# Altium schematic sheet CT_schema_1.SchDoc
size 445 x 258 mm
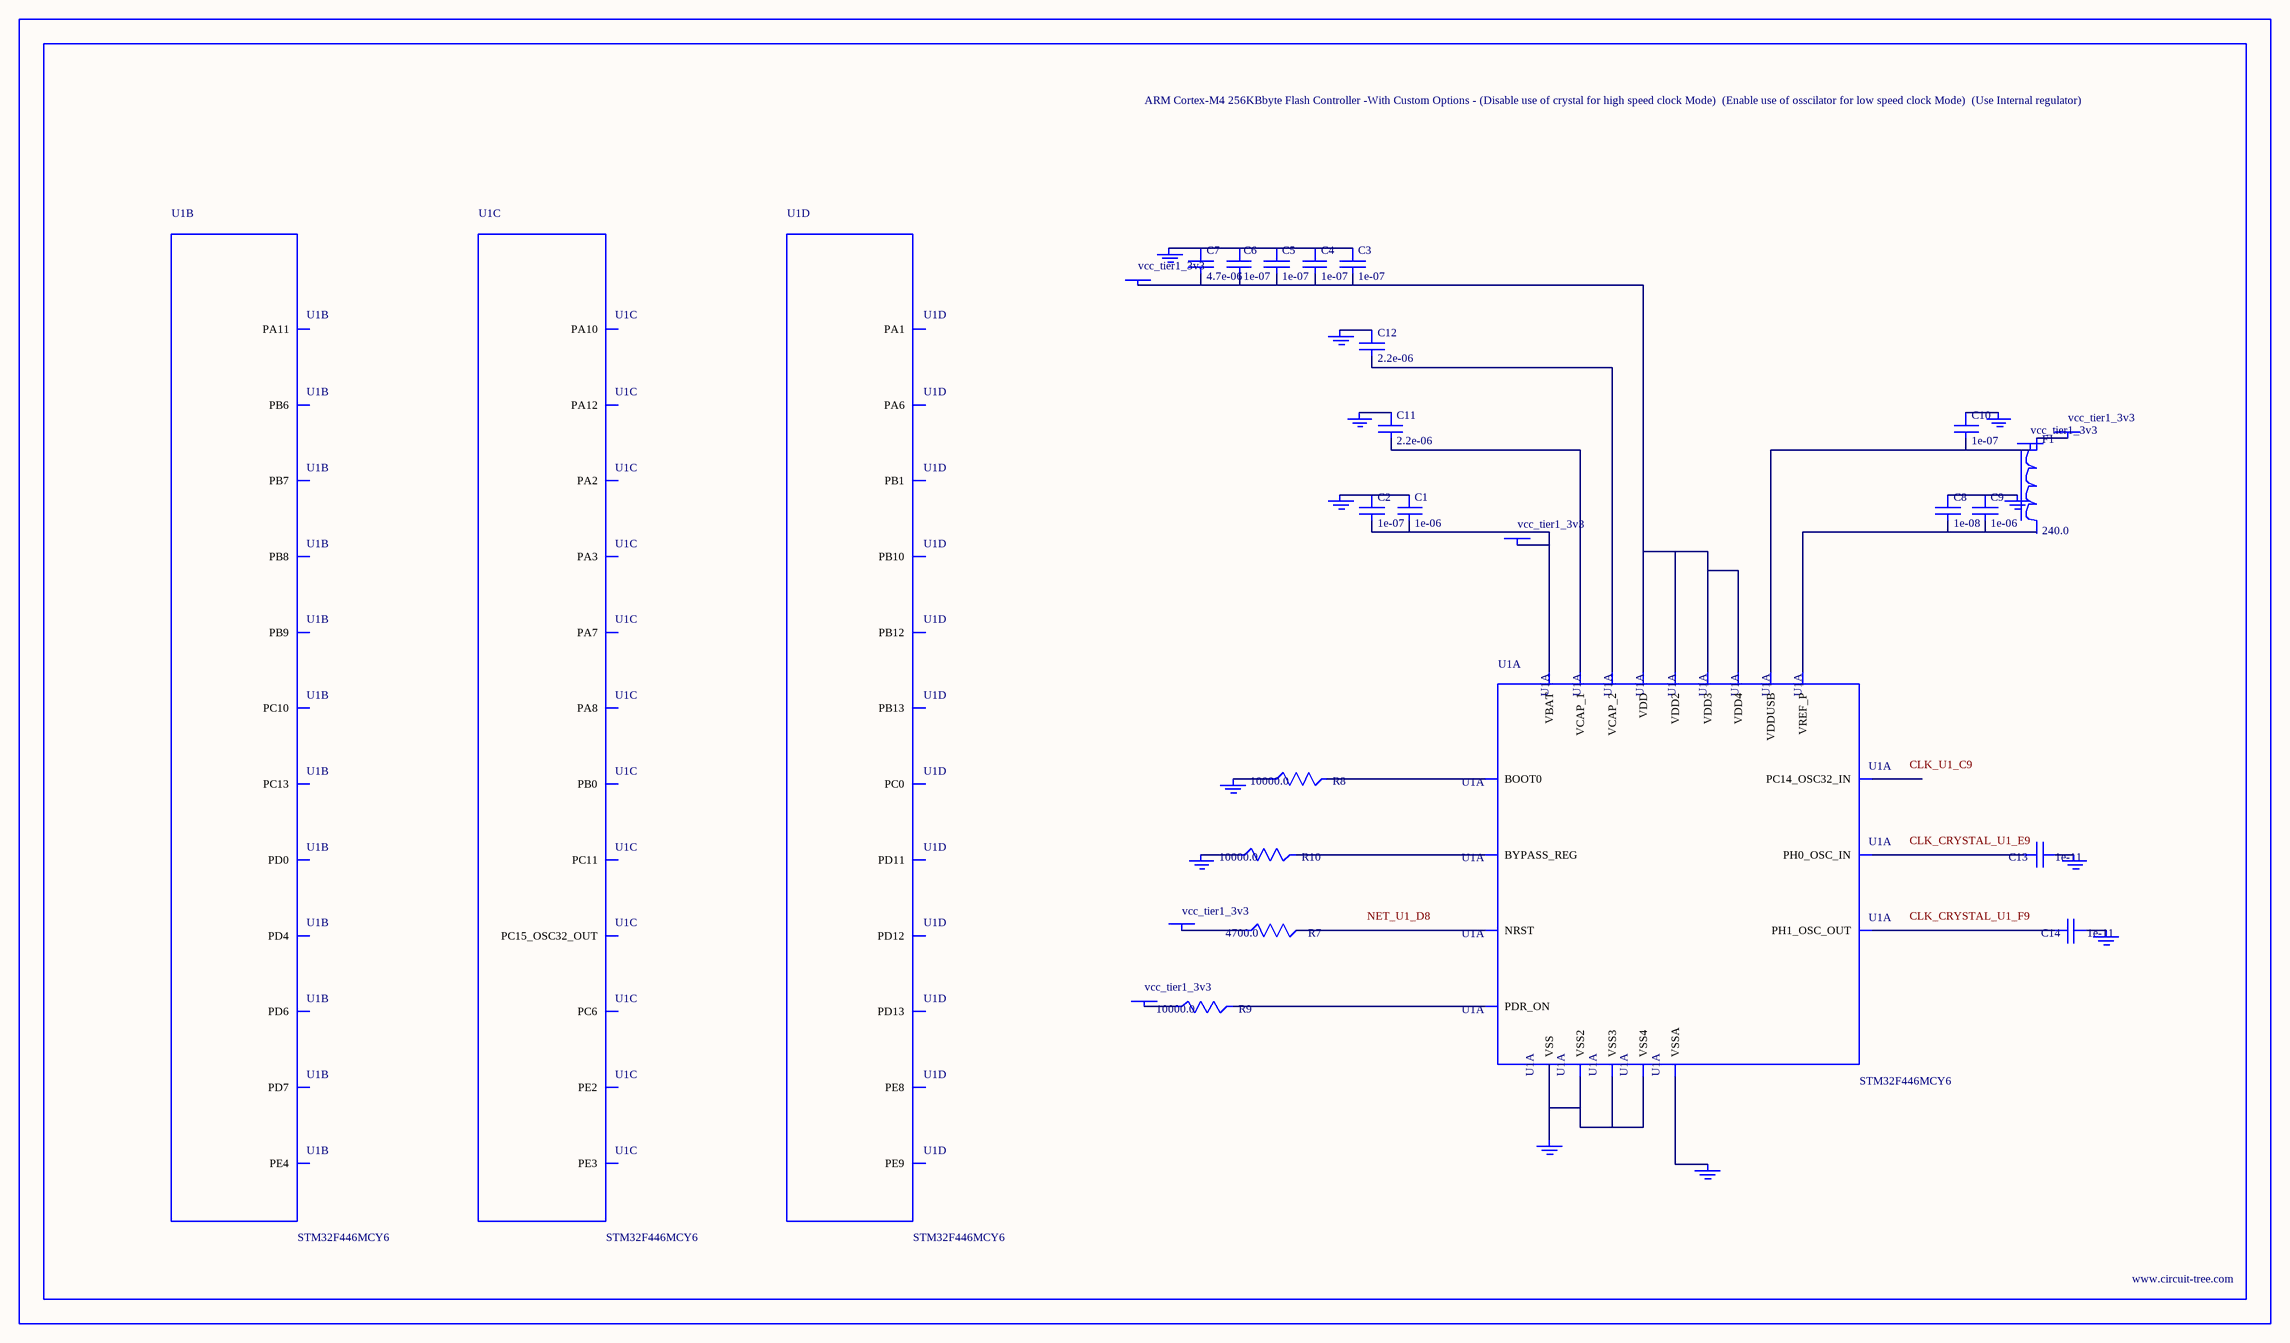
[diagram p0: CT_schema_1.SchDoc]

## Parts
BORDER0  (no value)
C1  1e-06  [C0603]
C2  1e-07  [C0603]
C3  1e-07  [C0603]
C4  1e-07  [C0603]
C5  1e-07  [C0603]
C6  1e-07  [C0603]
C7  4.7e-06  [C0603]
C8  1e-08  [C0603]
C9  1e-06  [C0603]
C10  1e-07  [C0603]
C11  2.2e-06  [C0603]
C12  2.2e-06  [C0603]
C13  1e-11  [C0402]
C14  1e-11  [C0402]
F1  240.0  [L0603]
GND_INSTANCE_0_0  (no value)
GND_INSTANCE_0_1  (no value)
GND_INSTANCE_0_2  (no value)
GND_INSTANCE_0_3  (no value)
GND_INSTANCE_0_4  (no value)
GND_INSTANCE_0_5  (no value)
GND_INSTANCE_0_6  (no value)
GND_INSTANCE_0_7  (no value)
GND_INSTANCE_0_8  (no value)
GND_INSTANCE_0_9  (no value)
GND_INSTANCE_0_10  (no value)
GND_INSTANCE_0_11  (no value)
POWER_INSTANCE_0_0  vcc_tier1_3v3
POWER_INSTANCE_0_1  vcc_tier1_3v3
POWER_INSTANCE_0_2  vcc_tier1_3v3
POWER_INSTANCE_0_3  vcc_tier1_3v3
POWER_INSTANCE_0_4  vcc_tier1_3v3
POWER_INSTANCE_0_5  vcc_tier1_3v3
R7  4700.0  [R0603]
R8  10000.0  [R0603]
R9  10000.0  [R0603]
R10  10000.0  [R0603]
U1  STM32F446MCY6  [WLCSP81]  (parts A,B,C,D of 9)

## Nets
NetC1_1: C1.1 C2.1 GND_INSTANCE_0_0.0(GND)
NetC1_2: C1.2 C2.2 POWER_INSTANCE_0_0.0(PWR) U1.B9(VBAT)
NetC3_1: C3.1 C4.1 C5.1 C6.1 C7.1 GND_INSTANCE_0_1.0(GND)
NetC3_2: C3.2 C4.2 C5.2 C6.2 C7.2 POWER_INSTANCE_0_1.0(PWR) U1.A1(VDD) U1.A8(VDD2) U1.H9(VDD3) U1.J2(VDD4)
NetC8_1: C8.1 C9.1 GND_INSTANCE_0_3.0(GND)
NetC8_2: C8.2 C9.2 U1.H8(VREF_P)
NetC10_1: C10.1 GND_INSTANCE_0_4.0(GND)
NetC10_2: C10.2 POWER_INSTANCE_0_4.0(PWR) U1.E1(VDDUSB)
NetC11_1: C11.1 GND_INSTANCE_0_6.0(GND)
NetC11_2: C11.2 U1.J3(VCAP_1)
NetC12_1: C12.1 GND_INSTANCE_0_7.0(GND)
NetC12_2: C12.2 U1.C2(VCAP_2)
NetC13_1: C13.1 GND_INSTANCE_0_8.0(GND)
NetC13_2: C13.2 U1.E9(PH0_OSC_IN)
NetC14_1: C14.1 GND_INSTANCE_0_9.0(GND)
NetC14_2: C14.2 U1.F9(PH1_OSC_OUT)
NetF1_1: F1.1 POWER_INSTANCE_0_2.0(PWR)
NetGND_INSTANCE_0_2_0: GND_INSTANCE_0_2.0(GND) R8.1
NetGND_INSTANCE_0_5_0: GND_INSTANCE_0_5.0(GND) R10.1
NetGND_INSTANCE_0_10_0: GND_INSTANCE_0_10.0(GND) U1.F7(VSSA)
NetGND_INSTANCE_0_11_0: GND_INSTANCE_0_11.0(GND) U1.B1(VSS) U1.B7(VSS2) U1.G8(VSS3) U1.H3(VSS4)
NetPOWER_INSTANCE_0_3_0: POWER_INSTANCE_0_3.0(PWR) R9.1
NetPOWER_INSTANCE_0_5_0: POWER_INSTANCE_0_5.0(PWR) R7.1
NetR7_2: R7.2 U1.D8(NRST)
NetR8_2: R8.2 U1.A7(BOOT0)
NetR9_2: R9.2 U1.B8(PDR_ON)
NetR10_2: R10.2 U1.J8(BYPASS_REG)

Not connected (* = marked no-connect by the designer): F1 2; U1 A3(PD4) A4(PD7) A9(PE4) B3(PD0) B4(PD6) B6(PB7) C1(PA11) C5(PB6) C6(PB8) C7(PB9) C8(PC13) C9(PC14_OSC32_IN) D3(PC10) D4(PC11) D6(PE3) D7(PE2) D9(PC15_OSC32_OUT) E2(PA8) E3(PA10) E4(PA12) E5(PA7) E6(PA3) E7(PA2) F1(PC6) F5(PB0) G1(PD13) G2(PD12) G4(PB12) G5(PE9) G6(PA6) G7(PA1) G9(PC0) H1(PD11) H2(PB13) H4(PB10) H5(PE8) H6(PB1)

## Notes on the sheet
- Labels drawn without touching a wire or pin: CLK_CRYSTAL_U1_E9, CLK_CRYSTAL_U1_F9, CLK_U1_C9, NET_U1_D8

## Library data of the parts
BORDER0 = BORDER_PAGE0
C1 C9 = C0603C105K3RACTU
C2-C6 C10 = 06035C104K4Z2A
C7 = GRM188R6YA475KE15D
C8 = 06035C103K4Z2A
C11 C12 = C0603C225K8RACTU
C13 C14 = C0402C100K3GACTU
F1 = Z0603C241ASMST
GND_INSTANCE_0_0-GND_INSTANCE_0_11 = GND
POWER_INSTANCE_0_0-POWER_INSTANCE_0_5 = PWR
R7 = RC0603JR-074K7L
R8-R10 = RC0603JR-0710KL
